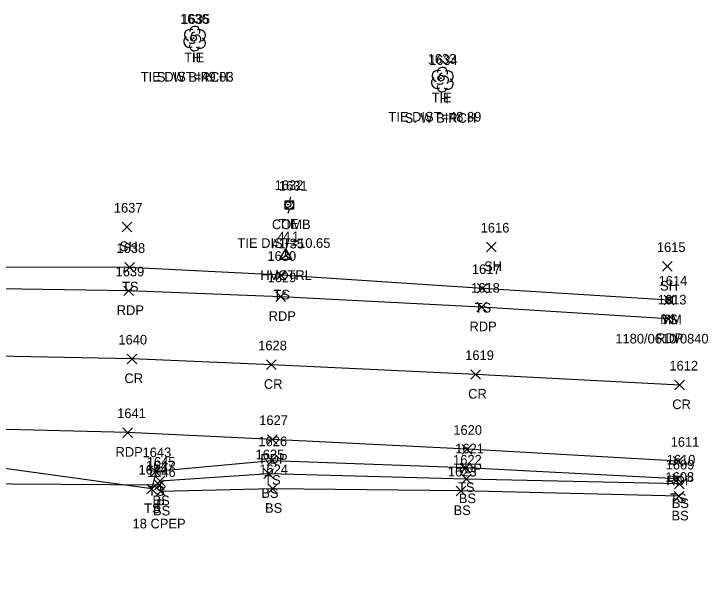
# Model space of a CAD drawing. Extents: x 1600395 to 1603269, y 874955 to 877143.
# Drawn here: x 1602264.7 to 1602408.6, y 875235.9 to 875353.7 of the extents above; entities that cross this region are included whole.
import ezdxf

# ---------------------------------------------------------------- set-up
doc = ezdxf.new("R2010")
doc.units = 0
for name, color, linetype in [('C_A', 7, 'Continuous'), ('C_C', 7, 'Continuous'), ('C_I', 7, 'Continuous'), ('CBP', 7, 'Continuous'), ('CPSM', 7, 'Continuous'), ('D_A', 7, 'Continuous'), ('D_C', 7, 'Continuous'), ('D_I', 7, 'Continuous'), ('D_TIC', 7, 'Continuous'), ('DCP', 7, 'Continuous'), ('L_A', 7, 'Continuous'), ('L_C', 7, 'Continuous'), ('L_I', 7, 'Continuous'), ('L_TIC', 7, 'Continuous'), ('LELB', 7, 'Continuous'), ('LTD', 7, 'Continuous'), ('P_A', 7, 'Continuous'), ('P_I', 7, 'Continuous'), ('P_TIC', 7, 'Continuous'), ('PET', 7, 'Continuous'), ('PRC', 7, 'Continuous'), ('S_A', 7, 'Continuous'), ('S_I', 7, 'Continuous'), ('SRM', 7, 'Continuous'), ('U_A', 7, 'Continuous'), ('U_C', 7, 'Continuous'), ('U_I', 7, 'Continuous'), ('UP', 7, 'Continuous')]:
    doc.layers.add(name, color=color, linetype=linetype)

msp = doc.modelspace()

# ---------------------------------------------------------------- linework, layer by layer
at = {"layer": 'CBP'}
for centre, radius in [((1602301.91, 875348.69), 0.625), ((1602301.91, 875348.69), 0.0833), ((1602353.19, 875340.39), 0.625), ((1602353.19, 875340.39), 0.0833), ((1602321.46, 875314.2), 0.625), ((1602321.46, 875314.2), 0.0833)]:
    msp.add_circle(centre, radius, dxfattribs=at)
at = {"layer": 'CPSM'}
for p, q in [((1602319.8, 875302.83), (1602321.05, 875305)), ((1602319.8, 875302.83), (1602321.05, 875305)), ((1602322.3, 875302.83), (1602321.05, 875305)), ((1602321.05, 875303.55), (1602321.05, 875305)), ((1602322.3, 875302.83), (1602321.05, 875305)), ((1602321.05, 875303.55), (1602321.05, 875305)), ((1602319.8, 875302.83), (1602321.05, 875303.55)), ((1602319.8, 875302.83), (1602321.05, 875303.55)), ((1602321.05, 875303.55), (1602321.05, 875303.55)), ((1602321.05, 875303.55), (1602322.3, 875302.83)), ((1602321.05, 875303.55), (1602321.05, 875303.55)), ((1602321.05, 875303.55), (1602322.3, 875302.83)), ((1602319.8, 875302.83), (1602322.3, 875302.83)), ((1602319.8, 875302.83), (1602322.3, 875302.83))]:
    msp.add_line(p, q, dxfattribs=at)
at = {"layer": 'D_TIC'}
for points in [[(1602293.81, 875255.02), (1602295.81, 875257.02)], [(1602295.81, 875255.02), (1602293.81, 875257.02)]]:
    msp.add_lwpolyline(points, dxfattribs=at)
at = {"layer": 'DCP'}
msp.add_lwpolyline([(1602294.81, 875256.02), (1602203.04, 875256.61)], dxfattribs=at)
at = {"layer": 'L_TIC'}
for points in [[(1602287.14, 875308.52), (1602289.14, 875310.52)], [(1602289.14, 875308.52), (1602287.14, 875310.52)], [(1602362.66, 875304.38), (1602364.66, 875306.38)], [(1602364.66, 875304.38), (1602362.66, 875306.38)], [(1602287.68, 875300.16), (1602289.68, 875302.16)], [(1602289.68, 875300.16), (1602287.68, 875302.16)], [(1602399.13, 875300.34), (1602401.13, 875302.34)], [(1602401.13, 875300.34), (1602399.13, 875302.34)], [(1602319.07, 875298.51), (1602321.07, 875300.51)], [(1602321.07, 875298.51), (1602319.07, 875300.51)], [(1602360.79, 875295.79), (1602362.79, 875297.79)], [(1602362.79, 875295.79), (1602360.79, 875297.79)], [(1602399.49, 875293.37), (1602401.49, 875295.37)], [(1602401.49, 875293.37), (1602399.49, 875295.37)], [(1602317.16, 875260.07), (1602319.16, 875262.07)], [(1602319.16, 875260.07), (1602317.16, 875262.07)], [(1602357.33, 875258.58), (1602359.33, 875260.58)], [(1602359.33, 875258.58), (1602357.33, 875260.58)], [(1602293.09, 875257.79), (1602295.09, 875259.79)], [(1602295.09, 875257.79), (1602293.09, 875259.79)], [(1602316.52, 875257.36), (1602318.52, 875259.36)], [(1602318.52, 875257.36), (1602316.52, 875259.36)], [(1602293.97, 875255.83), (1602295.97, 875257.83)], [(1602295.97, 875255.83), (1602293.97, 875257.83)], [(1602357.45, 875256.26), (1602359.45, 875258.26)], [(1602359.45, 875256.26), (1602357.45, 875258.26)], [(1602401.24, 875256.27), (1602403.24, 875258.27)], [(1602403.24, 875256.27), (1602401.24, 875258.27)], [(1602292.26, 875254.2), (1602294.26, 875256.2)], [(1602294.26, 875254.2), (1602292.26, 875256.2)], [(1602317.29, 875254.26), (1602319.29, 875256.26)], [(1602319.29, 875254.26), (1602317.29, 875256.26)], [(1602401.59, 875255.25), (1602403.59, 875257.25)], [(1602403.59, 875255.25), (1602401.59, 875257.25)], [(1602294.08, 875253.7), (1602296.08, 875255.7)], [(1602296.08, 875253.7), (1602294.08, 875255.7)], [(1602294.08, 875253.7), (1602296.08, 875255.7)], [(1602296.08, 875253.7), (1602294.08, 875255.7)], [(1602356.38, 875253.79), (1602358.38, 875255.79)], [(1602358.38, 875253.79), (1602356.38, 875255.79)], [(1602401.54, 875252.68), (1602403.54, 875254.68)], [(1602403.54, 875252.68), (1602401.54, 875254.68)]]:
    msp.add_lwpolyline(points, dxfattribs=at)
at = {"layer": 'LELB'}
for points in [[(1602400.49, 875294.37), (1602361.79, 875296.79), (1602320.07, 875299.51), (1602288.68, 875301.16), (1602257.59, 875301.18), (1602210.36, 875302.47), (1602169.51, 875304.24), (1602128.15, 875302.21), (1602094.95, 875298.42), (1602055.2, 875294.7), (1602015.81, 875291.56), (1601985.08, 875286.24), (1601964.25, 875289.69), (1601956.22, 875288.12), (1601952.74, 875279.27)], [(1602402.24, 875257.27), (1602358.33, 875259.58), (1602318.16, 875261.07), (1602294.09, 875258.79), (1602293.26, 875255.2), (1602257.7, 875260.11), (1602207.02, 875261.85), (1602194.04, 875260.01), (1602193.95, 875251.13)], [(1602402.59, 875256.25), (1602358.45, 875257.26), (1602317.52, 875258.36), (1602294.97, 875256.83), (1602295.08, 875254.7)], [(1602402.54, 875253.68), (1602357.38, 875254.79), (1602318.29, 875255.26), (1602295.08, 875254.7)]]:
    msp.add_lwpolyline(points, dxfattribs=at)
at = {"layer": 'LTD'}
for p, q in [((1602302.12, 875348.65), (1602302.12, 875348.65)), ((1602302.12, 875348.65), (1602302.12, 875348.65)), ((1602353.46, 875340.14), (1602353.46, 875340.14)), ((1602353.46, 875340.14), (1602353.46, 875340.14))]:
    msp.add_line(p, q, dxfattribs=at)
for centre in [(1602302.17, 875350.09), (1602353.51, 875341.58)]:
    msp.add_arc(centre, 1.05, 335.5272, 180.9563, dxfattribs=at)
for centre, major_axis, ratio, start_param, end_param in [((1602301.33, 875349.32), (1.21, -0.51), 0.895232, 1.570796, 4.712389), ((1602301.91, 875349.11), (-0.208, -0.792), 0.645439, 3.141593, 6.283185), ((1602303.16, 875349.24), (-1.14, -0.48), 0.949671, 1.570796, 4.712389), ((1602301.04, 875347.94), (0.58, -1.04), 0.959034, 3.141593, 6.283185), ((1602302.62, 875348.49), (-0.5, 0.667), 0.989748, 3.141593, 6.283185), ((1602303.12, 875347.82), (-1.09, 0.79), 0.841452, 1.570796, 4.712389), ((1602302.12, 875347.15), (0.26, 1.06), 0.942809, 1.570796, 4.712389), ((1602301.66, 875347.9), (-0.625, -0.083), 0.423636, 0, 3.141593), ((1602352.67, 875340.81), (1.21, -0.51), 0.895232, 1.570796, 4.712389), ((1602353.26, 875340.6), (-0.208, -0.792), 0.645439, 3.141593, 6.283185), ((1602353.96, 875339.98), (-0.5, 0.667), 0.989748, 3.141593, 6.283185), ((1602354.51, 875340.73), (-1.14, -0.48), 0.949671, 1.570796, 4.712389), ((1602352.38, 875339.44), (0.58, -1.04), 0.959034, 3.141593, 6.283185), ((1602353.01, 875339.39), (-0.625, -0.083), 0.423636, 0, 3.141593), ((1602354.46, 875339.31), (-1.09, 0.79), 0.841452, 1.570796, 4.712389), ((1602353.46, 875338.64), (0.26, 1.06), 0.942809, 1.570796, 4.712389)]:
    msp.add_ellipse(centre, major_axis=major_axis, ratio=ratio, start_param=start_param, end_param=end_param, dxfattribs=at)
at = {"layer": 'P_TIC'}
for points in [[(1602287.5, 875295.29), (1602289.5, 875297.29)], [(1602289.5, 875295.29), (1602287.5, 875297.29)], [(1602319.01, 875294.06), (1602321.01, 875296.06)], [(1602321.01, 875294.06), (1602319.01, 875296.06)], [(1602360.62, 875291.91), (1602362.62, 875293.91)], [(1602362.62, 875291.91), (1602360.62, 875293.91)], [(1602399.31, 875289.46), (1602401.31, 875291.46)], [(1602401.31, 875289.46), (1602399.31, 875291.46)], [(1602288.17, 875281.16), (1602290.17, 875283.16)], [(1602290.17, 875281.16), (1602288.17, 875283.16)], [(1602317.06, 875279.96), (1602319.06, 875281.96)], [(1602319.06, 875279.96), (1602317.06, 875281.96)], [(1602359.41, 875277.94), (1602361.41, 875279.94)], [(1602361.41, 875277.94), (1602359.41, 875279.94)], [(1602401.71, 875275.76), (1602403.71, 875277.76)], [(1602403.71, 875275.76), (1602401.71, 875277.76)], [(1602287.26, 875265.89), (1602289.26, 875267.89)], [(1602289.26, 875265.89), (1602287.26, 875267.89)], [(1602317.28, 875264.46), (1602319.28, 875266.46)], [(1602319.28, 875264.46), (1602317.28, 875266.46)], [(1602357.59, 875262.43), (1602359.59, 875264.43)], [(1602359.59, 875262.43), (1602357.59, 875264.43)], [(1602401.41, 875259.95), (1602403.41, 875261.95)], [(1602403.41, 875259.95), (1602401.41, 875261.95)]]:
    msp.add_lwpolyline(points, dxfattribs=at)
at = {"layer": 'PET'}
for points in [[(1602400.31, 875290.46), (1602361.62, 875292.91), (1602320.01, 875295.06), (1602288.5, 875296.29), (1602257.26, 875296.75), (1602210.13, 875296.36), (1602169.38, 875295.49), (1602128.8, 875293.68), (1602096.32, 875291.62), (1602056.86, 875287.91), (1602018.57, 875283.71), (1601986.25, 875279.93), (1601962.94, 875277.18), (1601953.76, 875275.85), (1601921.23, 875272), (1601886.39, 875267.75)], [(1602402.41, 875260.95), (1602358.59, 875263.43), (1602318.28, 875265.46), (1602288.26, 875266.89), (1602257.66, 875267.67), (1602209.91, 875267.9), (1602168.76, 875266.82), (1602131.43, 875265.02), (1602108.25, 875263.66), (1602076.07, 875260.92), (1602028.17, 875255.41), (1601981.36, 875249.81), (1601955.09, 875246.48), (1601931.43, 875243.62), (1601904.73, 875240.41), (1601882.14, 875236.79), (1601873.56, 875235.88), (1601879.64, 875251.36), (1601886.39, 875267.75)]]:
    msp.add_lwpolyline(points, dxfattribs=at)
at = {"layer": 'PRC'}
msp.add_lwpolyline([(1602402.71, 875276.76), (1602360.41, 875278.94), (1602318.06, 875280.96), (1602289.17, 875282.16), (1602257.66, 875282.81), (1602210.34, 875283), (1602169.35, 875282.18), (1602129.85, 875280.43), (1602107.17, 875278.74), (1602075.28, 875276.04), (1602025.43, 875270.72), (1601983.16, 875265.3), (1601954.29, 875261.32), (1601930.37, 875258.06), (1601901.66, 875254.25), (1601879.64, 875251.36)], dxfattribs=at)
at = {"layer": 'SRM'}
msp.add_lwpolyline([(1602399.86, 875294.99), (1602401.11, 875294.99), (1602401.11, 875293.74), (1602399.86, 875293.74)], close=True, dxfattribs=at)
msp.add_circle((1602400.49, 875294.37), 0.0833, dxfattribs=at)
at = {"layer": 'UP'}
for p, q in [((1602322.03, 875315.75), (1602321.78, 875314.92)), ((1602320.94, 875313.25), (1602320.94, 875314.92)), ((1602320.94, 875314.92), (1602322.61, 875314.92)), ((1602321.78, 875314.08), (1602321.78, 875314.08)), ((1602322.61, 875314.92), (1602322.61, 875313.25)), ((1602322.61, 875313.25), (1602320.94, 875313.25)), ((1602321.53, 875312.42), (1602321.78, 875313.25))]:
    msp.add_line(p, q, dxfattribs=at)
msp.add_circle((1602321.78, 875314.08), 0.833, dxfattribs=at)

# ---------------------------------------------------------------- texts
at = {"layer": 'C_A'}
for s, p in [('TIE', (1602299.99, 875343.69)), ('TIE', (1602351.27, 875335.39)), ('TIE', (1602319.54, 875309.2)), ('HVCTRL', (1602315.75, 875298.55)), ('HVCTRL', (1602315.75, 875298.55))]:
    msp.add_text(s, height=2, dxfattribs=at).set_placement(p)
at = {"layer": 'C_C'}
for s, p in [('TIE DIST=49.03', (1602290.97, 875339.69)), ('TIE DIST=48.89', (1602342.32, 875331.39)), ('TIE DIST=10.65', (1602311.03, 875305.2))]:
    msp.add_text(s, height=2, dxfattribs=at).set_placement(p)
at = {"layer": 'C_I'}
for s, p in [('1636', (1602299.12, 875351.69)), ('1633', (1602350.45, 875343.39)), ('1632', (1602318.72, 875317.2)), ('4_1', (1602319.34, 875306.55)), ('4', (1602320.49, 875306.55))]:
    msp.add_text(s, height=2, dxfattribs=at).set_placement(p)
at = {"layer": 'D_A'}
msp.add_text('P', height=2, dxfattribs=at).set_placement((1602294.19, 875251.02))
at = {"layer": 'D_C'}
msp.add_text('18 CPEP', height=2, dxfattribs=at).set_placement((1602289.28, 875247.02))
at = {"layer": 'D_I'}
msp.add_text('1647', height=2, dxfattribs=at).set_placement((1602292.07, 875259.02))
at = {"layer": 'L_A'}
for s, p in [('H', (1602301.56, 875343.65)), ('H', (1602352.9, 875335.14)), ('SH', (1602286.63, 875304.52)), ('SH', (1602362.15, 875300.38)), ('TS', (1602287.09, 875296.16)), ('SH', (1602398.61, 875296.34)), ('TS', (1602318.48, 875294.51)), ('TS', (1602360.2, 875291.79)), ('TS', (1602398.89, 875289.37)), ('TS', (1602316.57, 875256.07)), ('TS', (1602356.74, 875254.58)), ('TS', (1602292.5, 875253.79)), ('BS', (1602315.96, 875253.36)), ('BS', (1602293.42, 875251.83)), ('BS', (1602356.9, 875252.26)), ('TS', (1602400.65, 875252.27)), ('BS', (1602401.04, 875251.25)), ('TS', (1602291.67, 875250.2)), ('BS', (1602293.52, 875249.7)), ('BS', (1602293.52, 875249.7)), ('BS', (1602316.73, 875250.26)), ('BS', (1602355.82, 875249.79)), ('BS', (1602400.98, 875248.68))]:
    msp.add_text(s, height=2, dxfattribs=at).set_placement(p)
at = {"layer": 'L_C'}
for s, p in [('S. W BIRCH', (1602294.33, 875339.65)), ('S. W BIRCH', (1602345.67, 875331.14)), ('1180/0610/0840', (1602389.34, 875285.37))]:
    msp.add_text(s, height=2, dxfattribs=at).set_placement(p)
at = {"layer": 'L_I'}
for s, p in [('1635', (1602299.38, 875351.65)), ('1634', (1602350.72, 875343.14)), ('1637', (1602285.4, 875312.52)), ('1616', (1602361.43, 875308.38)), ('1638', (1602285.94, 875304.16)), ('1615', (1602397.95, 875304.34)), ('1630', (1602317.24, 875302.51)), ('1617', (1602359.61, 875299.79)), ('1614', (1602398.31, 875297.37)), ('1626', (1602315.36, 875264.07)), ('1643', (1602291.35, 875261.79)), ('1625', (1602314.78, 875261.36)), ('1621', (1602356.16, 875262.58)), ('1645', (1602292.23, 875259.83)), ('1622', (1602355.71, 875260.26)), ('1610', (1602399.98, 875260.27)), ('1609', (1602399.77, 875259.25)), ('1644', (1602290.52, 875258.2)), ('1646', (1602292.28, 875257.7)), ('1646', (1602292.28, 875257.7)), ('1624', (1602315.55, 875258.26)), ('1623', (1602354.64, 875257.79)), ('1608', (1602399.72, 875256.68))]:
    msp.add_text(s, height=2, dxfattribs=at).set_placement(p)
at = {"layer": 'P_A'}
for s, p in [('RDP', (1602285.99, 875291.29)), ('RDP', (1602317.49, 875290.06)), ('RDP', (1602359.11, 875287.91)), ('RDP', (1602397.8, 875285.46)), ('CR', (1602287.6, 875277.16)), ('CR', (1602316.5, 875275.96)), ('CR', (1602358.84, 875273.94)), ('CR', (1602401.14, 875271.76)), ('RDP', (1602285.75, 875261.89)), ('RDP', (1602315.77, 875260.46)), ('RDP', (1602356.07, 875258.43)), ('RDP', (1602399.9, 875255.95))]:
    msp.add_text(s, height=2, dxfattribs=at).set_placement(p)
at = {"layer": 'P_I'}
for s, p in [('1639', (1602285.75, 875299.29)), ('1629', (1602317.26, 875298.06)), ('1618', (1602359.45, 875295.91)), ('1613', (1602398.14, 875293.46)), ('1640', (1602286.34, 875285.16)), ('1628', (1602315.32, 875283.96)), ('1619', (1602358.23, 875281.94)), ('1612', (1602400.54, 875279.76)), ('1641', (1602286.09, 875269.89)), ('1627', (1602315.54, 875268.46)), ('1620', (1602355.76, 875266.43)), ('1611', (1602400.81, 875263.95))]:
    msp.add_text(s, height=2, dxfattribs=at).set_placement(p)
at = {"layer": 'S_A'}
msp.add_text('MM', height=2, dxfattribs=at).set_placement((1602398.67, 875289.37))
at = {"layer": 'S_I'}
msp.add_text('1614', height=2, dxfattribs=at).set_placement((1602398.31, 875297.37))
at = {"layer": 'U_A'}
msp.add_text('COMB', height=2, dxfattribs=at).set_placement((1602318.16, 875309.08))
at = {"layer": 'U_C'}
msp.add_text('#1/35', height=2, dxfattribs=at).set_placement((1602318.11, 875305.08))
at = {"layer": 'U_I'}
msp.add_text('1631', height=2, dxfattribs=at).set_placement((1602319.61, 875317.08))

doc.saveas('drawing.dxf')
